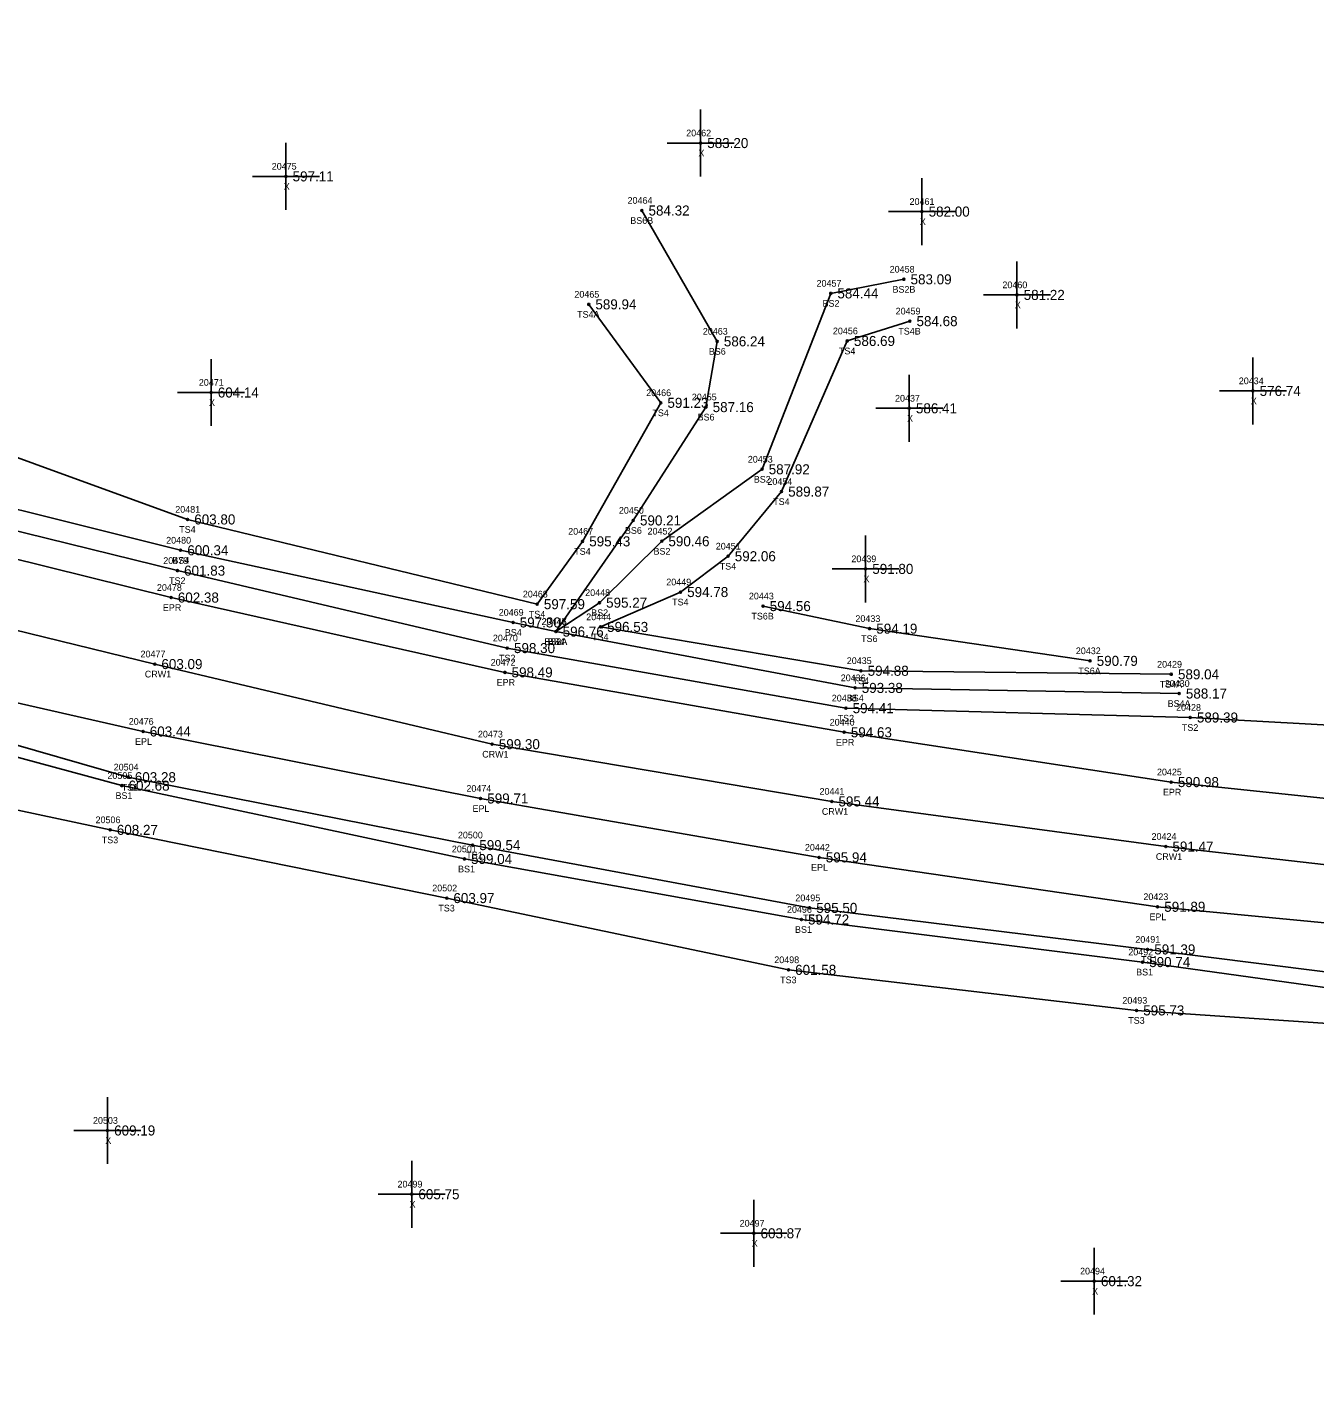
# Model space of a CAD drawing. Extents: x 1530159 to 1531652, y 877045 to 877724.
# Drawn here: x 1530389 to 1530581.3, y 877194.6 to 877399.7 of the extents above; entities that cross this region are included whole.
import ezdxf

# ---------------------------------------------------------------- set-up
doc = ezdxf.new("R2010")
doc.units = 0
for name, color, linetype in [('RD_DTM_BkLn1', 7, 'Continuous'), ('RD_DTM_BkLn2', 7, 'Continuous'), ('RD_DTM_BkLn_txCode', 7, 'Continuous'), ('RD_EX_Misc', 7, 'Continuous'), ('RD_EX_Misc_txCode', 7, 'Continuous'), ('RD_EX_Road', 7, 'Continuous'), ('RD_EX_Road_txCode', 7, 'Continuous'), ('RD_EX_TX_Misc_ELEV', 7, 'Continuous'), ('RD_EX_TX_Road_ELEV', 7, 'Continuous'), ('RD_HC_Survey_ELEV', 7, 'Continuous'), ('RD_HC_Survey_txCode', 7, 'Continuous'), ('RD_SMD_Locator', 7, 'Continuous')]:
    doc.layers.add(name, color=color, linetype=linetype)

msp = doc.modelspace()

# ---------------------------------------------------------------- linework, layer by layer
at = {"layer": 'RD_DTM_BkLn1'}
msp.add_lwpolyline([(1530865.56, 877271.01), (1530814.96, 877268.2), (1530763.15, 877267.89), (1530711.13, 877268.14), (1530659.67, 877269.22), (1530608.85, 877271.65), (1530559.07, 877277.33), (1530509.18, 877284.07), (1530458.44, 877292.62), (1530408.04, 877304.59), (1530358.54, 877316.67), (1530308.57, 877330.02), (1530250.23, 877350.32), (1530188.17, 877372.62)], dxfattribs=at)
at = {"layer": 'RD_DTM_BkLn2'}
for points in [[(1530472.87, 877358.33), (1530483.63, 877343.62), (1530471.95, 877322.92), (1530465.17, 877313.54), (1530412.95, 877326.2), (1530367.19, 877342.84), (1530314.9, 877359.43), (1530309.6, 877379.3), (1530304.43, 877399.7)], [(1530467.98, 877309.44), (1530479.53, 877326.05), (1530490.39, 877342.98), (1530492.06, 877352.8), (1530480.81, 877372.35)], [(1530467.98, 877309.44), (1530474.47, 877313.76), (1530483.78, 877322.94), (1530498.76, 877333.69), (1530509.02, 877359.97), (1530519.95, 877362.07)], [(1530846.55, 877195.51), (1530836.44, 877218.02), (1530825.43, 877234.54), (1530809.73, 877254.08), (1530787.3, 877254.89), (1530761.32, 877254.01), (1530707.75, 877254.4), (1530659.82, 877254.09), (1530608.22, 877255.41), (1530556.36, 877261.96), (1530505.86, 877268.16), (1530455.53, 877277.54), (1530404.07, 877287.69), (1530355.59, 877301.63), (1530305.18, 877312.26), (1530242.86, 877334.32), (1530183.05, 877357.3)], [(1530843.03, 877194.57), (1530830.04, 877216.97), (1530814.8, 877230.65), (1530802.93, 877234.88), (1530787.62, 877244.18), (1530761.15, 877248.01), (1530710.15, 877249.2), (1530659.29, 877248.38), (1530607.91, 877252.81), (1530555.6, 877260.07), (1530504.64, 877266.43), (1530454.3, 877275.47), (1530403.13, 877286.43), (1530354.95, 877299.51), (1530304.97, 877310.18), (1530241.94, 877332.54), (1530182.43, 877355.46)], [(1530559.9, 877303.06), (1530513.54, 877303.59), (1530474.62, 877310.14), (1530486.58, 877315.35), (1530493.69, 877320.7), (1530501.67, 877330.36), (1530511.49, 877352.86), (1530520.84, 877355.82)], [(1530780.69, 877332.06), (1530788.09, 877307.32), (1530788.66, 877295.54), (1530766.14, 877289.81), (1530711.07, 877289.67), (1530661.26, 877292.24), (1530608.81, 877294.06), (1530562.73, 877296.61), (1530511.3, 877298), (1530460.71, 877306.98), (1530411.43, 877318.55), (1530362.64, 877330.57), (1530303.69, 877348.12), (1530304.27, 877353.11), (1530308.16, 877353.44)], [(1530561.08, 877300.19), (1530512.66, 877301.03), (1530467.98, 877309.44), (1530461.57, 877310.81), (1530411.91, 877321.59), (1530363.99, 877333.54), (1530305.21, 877351.73)], [(1530547.76, 877305.07), (1530514.83, 877309.88), (1530498.91, 877313.25)], [(1530781.59, 877237.74), (1530769.19, 877234.54), (1530707.91, 877235.08), (1530658.9, 877217.43), (1530601.44, 877222.78), (1530585.47, 877250.74), (1530554.71, 877252.85), (1530502.71, 877258.91), (1530451.66, 877269.63), (1530401.38, 877279.82), (1530344.51, 877291.95), (1530339.77, 877285.8), (1530357.81, 877267.08), (1530377.75, 877244.03)]]:
    msp.add_lwpolyline(points, dxfattribs=at)
at = {"layer": 'RD_EX_Misc'}
for p, q in [((1530489.58, 877377.43), (1530489.58, 877387.43)), ((1530427.64, 877372.45), (1530427.64, 877382.45)), ((1530484.58, 877382.43), (1530494.58, 877382.43)), ((1530422.64, 877377.45), (1530432.64, 877377.45)), ((1530522.65, 877367.19), (1530522.65, 877377.19)), ((1530517.65, 877372.19), (1530527.65, 877372.19)), ((1530536.85, 877354.74), (1530536.85, 877364.74)), ((1530531.85, 877359.74), (1530541.85, 877359.74)), ((1530416.46, 877340.16), (1530416.46, 877350.16)), ((1530572.1, 877340.4), (1530572.1, 877350.4)), ((1530520.75, 877337.8), (1530520.75, 877347.8)), ((1530411.46, 877345.16), (1530421.46, 877345.16)), ((1530567.1, 877345.4), (1530577.1, 877345.4)), ((1530515.75, 877342.8), (1530525.75, 877342.8)), ((1530514.23, 877313.81), (1530514.23, 877323.81)), ((1530509.23, 877318.81), (1530519.23, 877318.81)), ((1530400.98, 877229.91), (1530400.98, 877239.91)), ((1530395.98, 877234.91), (1530405.98, 877234.91)), ((1530446.43, 877220.39), (1530446.43, 877230.39)), ((1530441.43, 877225.39), (1530451.43, 877225.39)), ((1530497.54, 877214.55), (1530497.54, 877224.55)), ((1530492.54, 877219.55), (1530502.54, 877219.55)), ((1530548.39, 877207.4), (1530548.39, 877217.4)), ((1530543.39, 877212.4), (1530553.39, 877212.4))]:
    msp.add_line(p, q, dxfattribs=at)
at = {"layer": 'RD_EX_Road'}
for points in [[(1530865.35, 877283.66), (1530865.36, 877280.61), (1530815.01, 877277.89), (1530763.54, 877277.33), (1530711.24, 877277.01), (1530660.64, 877277.93), (1530609.51, 877281.74), (1530559.88, 877286.96), (1530511.03, 877294.4), (1530460.35, 877303.35), (1530410.49, 877314.53), (1530361.04, 877326.77), (1530310.59, 877340.83), (1530305.81, 877342.41), (1530288.71, 877347.95), (1530253.55, 877359.27), (1530192.32, 877382.67)], [(1530866.41, 877261.44), (1530852.87, 877260.97), (1530806.23, 877259.4), (1530762.44, 877259.05), (1530711.8, 877259.77), (1530659.89, 877260.87), (1530608.32, 877263.5), (1530557.85, 877268.33), (1530507.29, 877275.71), (1530456.72, 877284.51), (1530406.3, 877294.52), (1530356.75, 877305.76), (1530307.05, 877320.51), (1530246, 877341.34), (1530185.26, 877363.97)]]:
    msp.add_lwpolyline(points, dxfattribs=at)
at = {"layer": 'RD_SMD_Locator'}
for centre in [(1530489.58, 877382.43), (1530427.64, 877377.45), (1530480.81, 877372.35), (1530522.65, 877372.19), (1530519.95, 877362.07), (1530472.87, 877358.33), (1530509.02, 877359.97), (1530536.85, 877359.74), (1530520.84, 877355.82), (1530492.06, 877352.8), (1530511.49, 877352.86), (1530416.46, 877345.16), (1530572.1, 877345.4), (1530483.63, 877343.62), (1530490.39, 877342.98), (1530520.75, 877342.8), (1530498.76, 877333.69), (1530501.67, 877330.36), (1530412.95, 877326.2), (1530479.53, 877326.05), (1530411.91, 877321.59), (1530471.95, 877322.92), (1530483.78, 877322.94), (1530493.69, 877320.7), (1530411.43, 877318.55), (1530514.23, 877318.81), (1530486.58, 877315.35), (1530410.49, 877314.53), (1530465.17, 877313.54), (1530474.47, 877313.76), (1530498.91, 877313.25), (1530461.57, 877310.81), (1530467.98, 877309.44), (1530467.98, 877309.44), (1530467.98, 877309.44), (1530474.62, 877310.14), (1530514.83, 877309.88), (1530460.71, 877306.98), (1530547.76, 877305.07), (1530408.04, 877304.59), (1530460.35, 877303.35), (1530513.54, 877303.59), (1530559.9, 877303.06), (1530512.66, 877301.03), (1530561.08, 877300.19), (1530511.3, 877298), (1530562.73, 877296.61), (1530406.3, 877294.52), (1530458.44, 877292.62), (1530511.03, 877294.4), (1530403.13, 877286.43), (1530404.07, 877287.69), (1530559.88, 877286.96), (1530456.72, 877284.51), (1530509.18, 877284.07), (1530401.38, 877279.82), (1530455.53, 877277.54), (1530559.07, 877277.33), (1530454.3, 877275.47), (1530507.29, 877275.71), (1530451.66, 877269.63), (1530505.86, 877268.16), (1530557.85, 877268.33), (1530504.64, 877266.43), (1530556.36, 877261.96), (1530555.6, 877260.07), (1530502.71, 877258.91), (1530554.71, 877252.85), (1530400.98, 877234.91), (1530446.43, 877225.39), (1530497.54, 877219.55), (1530548.39, 877212.4)]:
    msp.add_circle(centre, 0.15, dxfattribs=at)

# ---------------------------------------------------------------- texts
at = {"layer": 'RD_DTM_BkLn_txCode'}
for s, p in [('20464', (1530478.67, 877373.35)), ('BS6B', (1530479.08, 877370.35)), ('20458', (1530517.83, 877363.07)), ('20457', (1530506.91, 877360.97)), ('BS2B', (1530518.25, 877360.07)), ('20465', (1530470.73, 877359.33)), ('BS2', (1530507.8, 877357.97)), ('TS4A', (1530471.14, 877356.33)), ('20459', (1530518.72, 877356.82)), ('20463', (1530489.92, 877353.8)), ('20456', (1530509.35, 877353.86)), ('TS4B', (1530519.12, 877353.82)), ('BS6', (1530490.81, 877350.8)), ('TS4', (1530510.25, 877350.86)), ('20466', (1530481.46, 877344.62)), ('20455', (1530488.27, 877343.98)), ('TS4', (1530482.39, 877341.62)), ('BS6', (1530489.14, 877340.98)), ('20453', (1530496.64, 877334.69)), ('BS2', (1530497.53, 877331.69)), ('20454', (1530499.56, 877331.36)), ('20481', (1530411.11, 877327.2)), ('20450', (1530477.38, 877327.05)), ('TS4', (1530500.43, 877328.36)), ('20480', (1530409.75, 877322.59)), ('TS4', (1530411.7, 877324.2)), ('20467', (1530469.81, 877323.92)), ('BS6', (1530478.28, 877324.05)), ('20452', (1530481.66, 877323.94)), ('TS4', (1530470.71, 877320.92)), ('BS2', (1530482.55, 877320.94)), ('20451', (1530491.85, 877321.7)), ('20479', (1530409.32, 877319.55)), ('BS4', (1530410.68, 877319.59)), ('TS4', (1530492.44, 877318.7)), ('TS2', (1530410.19, 877316.55)), ('20449', (1530484.46, 877316.35)), ('20468', (1530463.03, 877314.54)), ('20448', (1530472.35, 877314.76)), ('TS4', (1530485.33, 877313.35)), ('20443', (1530496.8, 877314.25)), ('20469', (1530459.43, 877311.81)), ('TS4', (1530463.93, 877311.54)), ('20446', (1530465.83, 877310.44)), ('20445', (1530465.86, 877310.44)), ('20447', (1530465.86, 877310.44)), ('20444', (1530472.5, 877311.14)), ('BS2', (1530473.24, 877311.76)), ('TS6B', (1530497.17, 877311.25)), ('20433', (1530512.71, 877310.88)), ('BS4', (1530460.34, 877308.81)), ('TS4', (1530473.38, 877308.14)), ('20470', (1530458.56, 877307.98)), ('BS6A', (1530466.24, 877307.44)), ('BS2A', (1530466.26, 877307.44)), ('BS4', (1530466.75, 877307.44)), ('TS6', (1530513.56, 877307.88)), ('20432', (1530545.64, 877306.07)), ('TS2', (1530459.47, 877304.98)), ('20435', (1530511.42, 877304.59)), ('20429', (1530557.78, 877304.06)), ('20436', (1530510.52, 877302.03)), ('TS6A', (1530546.01, 877303.07)), ('TS4', (1530512.3, 877301.59)), ('TS4A', (1530558.17, 877301.06)), ('20430', (1530558.92, 877301.19)), ('20438', (1530509.18, 877299)), ('BS4', (1530511.43, 877299.03)), ('BS4A', (1530559.36, 877298.19)), ('TS2', (1530510.06, 877296)), ('20428', (1530560.61, 877297.61)), ('TS2', (1530561.48, 877294.61)), ('20504', (1530401.91, 877288.69)), ('20505', (1530400.97, 877287.43)), ('TS1', (1530403.11, 877285.69)), ('BS1', (1530402.18, 877284.43)), ('20506', (1530399.2, 877280.82)), ('TS3', (1530400.13, 877277.82)), ('20500', (1530453.33, 877278.54)), ('20501', (1530452.43, 877276.47)), ('TS1', (1530454.57, 877275.54)), ('BS1', (1530453.36, 877273.47)), ('20502', (1530449.5, 877270.63)), ('20495', (1530503.74, 877269.16)), ('TS3', (1530450.41, 877267.63)), ('20496', (1530502.49, 877267.43)), ('TS1', (1530504.89, 877266.16)), ('BS1', (1530503.69, 877264.43)), ('20492', (1530553.48, 877261.07)), ('20491', (1530554.53, 877262.96)), ('20498', (1530500.59, 877259.91)), ('TS1', (1530555.4, 877259.96)), ('TS3', (1530501.46, 877256.91)), ('BS1', (1530554.65, 877258.07)), ('20493', (1530552.59, 877253.85)), ('TS3', (1530553.47, 877250.85))]:
    msp.add_text(s, height=1, dxfattribs=at).set_placement(p)
at = {"layer": 'RD_EX_Misc_txCode'}
for s, p in [('20462', (1530487.44, 877383.43)), ('X', (1530489.26, 877380.43)), ('20475', (1530425.52, 877378.45)), ('X', (1530427.32, 877375.45)), ('20461', (1530520.8, 877373.19)), ('X', (1530522.34, 877370.19)), ('20460', (1530534.67, 877360.74)), ('X', (1530536.53, 877357.74)), ('20471', (1530414.63, 877346.16)), ('20434', (1530569.98, 877346.4)), ('X', (1530416.15, 877343.16)), ('20437', (1530518.63, 877343.8)), ('X', (1530571.78, 877343.4)), ('X', (1530520.43, 877340.8)), ('20439', (1530512.11, 877319.81)), ('X', (1530513.92, 877316.81)), ('20503', (1530398.82, 877235.91)), ('X', (1530400.66, 877232.91)), ('20499', (1530444.31, 877226.39)), ('X', (1530446.11, 877223.39)), ('20497', (1530495.42, 877220.55)), ('X', (1530497.23, 877217.55)), ('20494', (1530546.27, 877213.4)), ('X', (1530548.08, 877210.4))]:
    msp.add_text(s, height=1, dxfattribs=at).set_placement(p)
at = {"layer": 'RD_EX_Road_txCode'}
for s, p in [('20478', (1530408.37, 877315.53)), ('EPR', (1530409.26, 877312.53)), ('20472', (1530458.23, 877304.35)), ('EPR', (1530459.12, 877301.35)), ('20476', (1530404.16, 877295.52)), ('20440', (1530508.87, 877295.4)), ('EPL', (1530405.1, 877292.52)), ('EPR', (1530509.8, 877292.4)), ('20425', (1530557.76, 877287.96)), ('20474', (1530454.6, 877285.51)), ('EPR', (1530558.65, 877284.96)), ('EPL', (1530455.51, 877282.51)), ('20442', (1530505.17, 877276.71)), ('EPL', (1530506.09, 877273.71)), ('20423', (1530555.73, 877269.33)), ('EPL', (1530556.64, 877266.33))]:
    msp.add_text(s, height=1, dxfattribs=at).set_placement(p)
at = {"layer": 'RD_EX_TX_Misc_ELEV'}
for s, p in [('583.20', (1530490.58, 877381.68)), ('597.11', (1530428.64, 877376.7)), ('584.32', (1530481.81, 877371.6)), ('582.00', (1530523.65, 877371.44)), ('583.09', (1530520.95, 877361.32)), ('584.44', (1530510.02, 877359.22)), ('581.22', (1530537.85, 877358.99)), ('589.94', (1530473.87, 877357.58)), ('584.68', (1530521.84, 877355.07)), ('586.24', (1530493.06, 877352.05)), ('586.69', (1530512.49, 877352.11)), ('576.74', (1530573.1, 877344.65)), ('604.14', (1530417.46, 877344.41)), ('591.23', (1530484.63, 877342.87)), ('587.16', (1530491.39, 877342.23)), ('586.41', (1530521.75, 877342.05)), ('587.92', (1530499.76, 877332.94)), ('589.87', (1530502.67, 877329.61)), ('603.80', (1530413.95, 877325.45)), ('590.21', (1530480.53, 877325.3)), ('595.43', (1530472.95, 877322.17)), ('590.46', (1530484.78, 877322.19)), ('600.34', (1530412.91, 877320.84)), ('592.06', (1530494.69, 877319.95)), ('591.80', (1530515.23, 877318.06)), ('601.83', (1530412.43, 877317.8)), ('594.78', (1530487.58, 877314.6)), ('597.59', (1530466.17, 877312.79)), ('595.27', (1530475.47, 877313.01)), ('594.56', (1530499.91, 877312.5)), ('597.30', (1530462.57, 877310.06)), ('596.76', (1530468.98, 877308.69)), ('596.76', (1530468.98, 877308.69)), ('596.76', (1530468.98, 877308.69)), ('596.53', (1530475.62, 877309.39)), ('594.19', (1530515.83, 877309.13)), ('598.30', (1530461.71, 877306.23)), ('590.79', (1530548.76, 877304.32)), ('594.88', (1530514.54, 877302.84)), ('589.04', (1530560.9, 877302.31)), ('593.38', (1530513.66, 877300.28)), ('588.17', (1530562.08, 877299.44)), ('594.41', (1530512.3, 877297.25)), ('589.39', (1530563.73, 877295.86)), ('602.68', (1530404.13, 877285.68)), ('603.28', (1530405.07, 877286.94)), ('608.27', (1530402.38, 877279.07)), ('599.54', (1530456.53, 877276.79)), ('599.04', (1530455.3, 877274.72)), ('603.97', (1530452.66, 877268.88)), ('595.50', (1530506.86, 877267.41)), ('594.72', (1530505.64, 877265.68)), ('591.39', (1530557.36, 877261.21)), ('590.74', (1530556.6, 877259.32)), ('601.58', (1530503.71, 877258.16)), ('595.73', (1530555.71, 877252.1)), ('609.19', (1530401.98, 877234.16)), ('605.75', (1530447.43, 877224.64)), ('603.87', (1530498.54, 877218.8)), ('601.32', (1530549.39, 877211.65))]:
    msp.add_text(s, height=1.5, dxfattribs=at).set_placement(p)
at = {"layer": 'RD_EX_TX_Road_ELEV'}
for s, p in [('602.38', (1530411.49, 877313.78)), ('598.49', (1530461.35, 877302.6)), ('603.44', (1530407.3, 877293.77)), ('594.63', (1530512.03, 877293.65)), ('590.98', (1530560.88, 877286.21)), ('599.71', (1530457.72, 877283.76)), ('595.94', (1530508.29, 877274.96)), ('591.89', (1530558.85, 877267.58))]:
    msp.add_text(s, height=1.5, dxfattribs=at).set_placement(p)
at = {"layer": 'RD_HC_Survey_ELEV'}
for s, p in [('603.09', (1530409.04, 877303.84)), ('599.30', (1530459.44, 877291.87)), ('595.44', (1530510.18, 877283.32)), ('591.47', (1530560.07, 877276.58))]:
    msp.add_text(s, height=1.5, dxfattribs=at).set_placement(p)
at = {"layer": 'RD_HC_Survey_txCode'}
for s, p in [('20477', (1530405.92, 877305.59)), ('CRW1', (1530406.56, 877302.59)), ('20473', (1530456.32, 877293.62)), ('CRW1', (1530456.96, 877290.62)), ('20441', (1530507.35, 877285.07)), ('CRW1', (1530507.7, 877282.07)), ('20424', (1530556.95, 877278.33)), ('CRW1', (1530557.59, 877275.33))]:
    msp.add_text(s, height=1, dxfattribs=at).set_placement(p)

doc.saveas('drawing.dxf')
